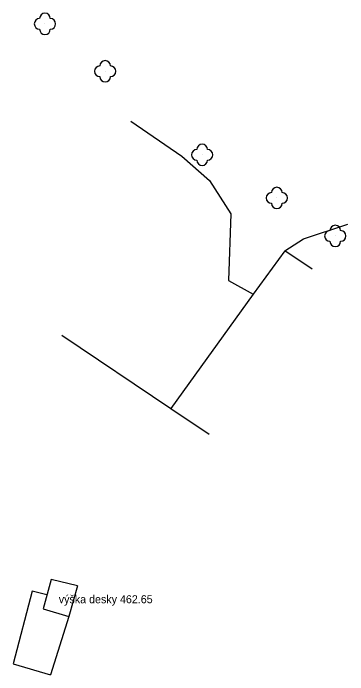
# Model space of a CAD drawing. Extents: x -747135 to -746147, y -1093269 to -1091735.
# Drawn here: x -746775.6 to -746744.2, y -1093268.8 to -1093206.8 of the extents above; entities that cross this region are included whole.
import ezdxf

# ---------------------------------------------------------------- set-up
doc = ezdxf.new("R2010")
doc.units = 0
for name, color, linetype in [('1016', 7, 'Continuous'), ('105', 7, 'Continuous'), ('305', 7, 'Continuous'), ('424', 7, 'Continuous'), ('803', 7, 'Continuous')]:
    doc.layers.add(name, color=color, linetype=linetype)

msp = doc.modelspace()

# ---------------------------------------------------------------- linework, layer by layer
at = {"layer": '1016'}
for points in [[(-746769.61, -1093260.43), (-746772.09, -1093259.84), (-746772.84, -1093262.58), (-746770.43, -1093263.31)], [(-746769.61, -1093260.43), (-746770.43, -1093263.31), (-746772.15, -1093268.77)], [(-746772.5, -1093261.28), (-746773.85, -1093260.93), (-746775.64, -1093267.76), (-746772.15, -1093268.77)]]:
    msp.add_lwpolyline(points, dxfattribs=at)
at = {"layer": '305'}
msp.add_lwpolyline([(-746750.17, -1093229.05), (-746753.13, -1093233.11)], dxfattribs=at)
at = {"layer": '424'}
for centre in [(-746772.66, -1093207.79), (-746767.01, -1093212.23), (-746757.91, -1093220.06), (-746750.91, -1093224.1), (-746745.42, -1093227.66)]:
    msp.add_circle(centre, 0.0005, dxfattribs=at)
for centre, start, end in [((-746772.66, -1093207.29), 0, 179.99999), ((-746773.16, -1093207.79), 89.99999, 269.99999), ((-746772.16, -1093207.79), 270, 89.99999), ((-746772.66, -1093208.29), 179.99999, 359.99999), ((-746767.01, -1093211.73), 0, 179.99999), ((-746767.51, -1093212.23), 89.99999, 269.99999), ((-746766.51, -1093212.23), 270, 89.99999), ((-746767.01, -1093212.73), 179.99999, 359.99999), ((-746757.91, -1093219.56), 0, 179.99999), ((-746758.41, -1093220.06), 89.99999, 269.99999), ((-746757.41, -1093220.06), 270, 89.99999), ((-746757.91, -1093220.56), 179.99999, 359.99999), ((-746751.41, -1093224.1), 89.99999, 269.99999), ((-746750.91, -1093223.6), 0, 179.99999), ((-746750.41, -1093224.1), 270, 89.99999), ((-746750.91, -1093224.6), 179.99999, 359.99999), ((-746745.42, -1093227.16), 0, 179.99999), ((-746745.92, -1093227.66), 89.99999, 269.99999), ((-746744.92, -1093227.66), 270, 89.99999), ((-746745.42, -1093228.16), 179.99999, 359.99999)]:
    msp.add_arc(centre, 0.5, start, end, dxfattribs=at)
at = {"layer": '803'}
for points in [[(-746764.61, -1093216.89), (-746759.83, -1093220.18), (-746757.22, -1093222.47), (-746755.21, -1093225.57), (-746755.43, -1093231.82), (-746753.13, -1093233.11)], [(-746750.17, -1093229.05), (-746748.42, -1093227.93), (-746744.25, -1093226.56)], [(-746747.59, -1093230.77), (-746750.17, -1093229.05)], [(-746753.13, -1093233.11), (-746760.85, -1093243.81)], [(-746771.09, -1093236.95), (-746760.85, -1093243.81), (-746757.26, -1093246.24)]]:
    msp.add_lwpolyline(points, dxfattribs=at)

# ---------------------------------------------------------------- texts
at = {"layer": '105'}
msp.add_text('výška desky 462.65', height=0.75, dxfattribs=at).set_placement((-746771.365, -1093262.069))

doc.saveas('drawing.dxf')
